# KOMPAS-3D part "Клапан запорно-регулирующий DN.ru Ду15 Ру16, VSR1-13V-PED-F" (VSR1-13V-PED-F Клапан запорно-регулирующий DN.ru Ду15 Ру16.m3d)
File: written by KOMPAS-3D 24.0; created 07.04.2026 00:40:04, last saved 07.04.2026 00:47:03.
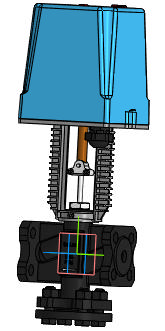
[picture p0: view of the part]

Document properties: Автор: R2D2; Полное имя файла: VSR1-13V-PED-F Клапан запорно-регулирующий DN.ru Ду15 Ру16.cdw

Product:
- Part/product: Клапан запорно-регулирующий DN.ru Ду15 Ру16  | designation VSR1-13V-PED-F
    Масса: 6.1
    Раздел спецификации: Прочие изделия
    Форматы листов документа: A3
    Примечание: D090-02879

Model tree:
1. Операция без истории:1  (labels: SHAPEOBJECT3D_ATTR_BUTT)

Expressions: VSR1-13V-PED-F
